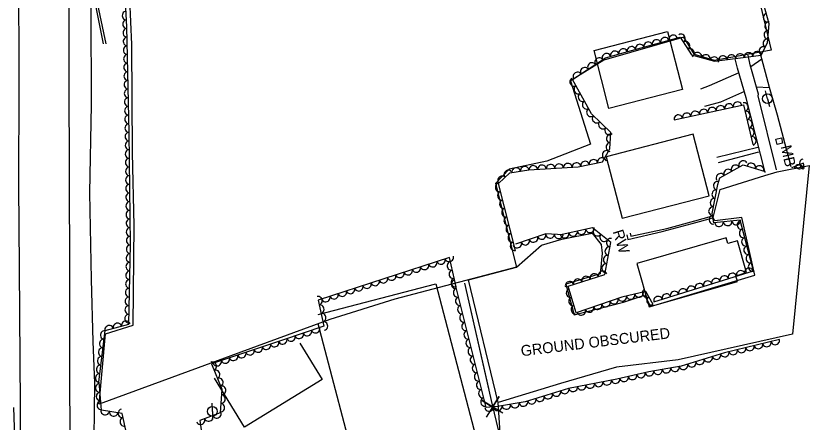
# Model space of a CAD drawing. Extents: x 1722896 to 1754269, y 648279 to 666297.
# Drawn here: x 1725769 to 1726135.7, y 663913.4 to 664101 of the extents above; entities that cross this region are included whole.
import ezdxf

# ---------------------------------------------------------------- set-up
doc = ezdxf.new("R2010")
doc.units = 0
for name, color, linetype in [('DESIGN - CENTERLINE - Proposed Text', 7, 'Continuous'), ('DESIGN - SCRATCH - User 1', 7, 'Continuous'), ('SURVEY - CENTERLINE - Preliminary', 7, 'Continuous'), ('SURVEY - CENTERLINE - Preliminary Text', 7, 'Continuous'), ('SURVEY - CONTROL with Text', 7, 'Continuous'), ('SURVEY - DTM - Breaklines', 7, 'Continuous'), ('SURVEY - VEGETATION - Features with Text', 7, 'Continuous')]:
    doc.layers.add(name, color=color, linetype=linetype)

msp = doc.modelspace()

# ---------------------------------------------------------------- linework, layer by layer
at = {"layer": 'DESIGN - CENTERLINE - Proposed Text'}
msp.add_line((1726121.95, 664043.1), (1726121.95, 664043.1), dxfattribs=at)
for points in [[(1726077.22, 664066.95), (1726043.19, 664058.18), (1726036.28, 664085), (1726070.31, 664093.78)], [(1726082.13, 664046.32), (1726041.93, 664035.87), (1726049.3, 664007.49), (1726089.51, 664017.94)], [(1726120.41, 664044.02), (1726122.89, 664044.59), (1726123.45, 664042.16), (1726120.97, 664041.58)], [(1726097.34, 663998.41), (1726056.04, 663986.6), (1726061.74, 663966.66), (1726102.63, 663978.35), (1726101.88, 663980.99), (1726106.83, 663982.41), (1726102.62, 663997.14), (1726098.07, 663995.84)]]:
    msp.add_lwpolyline(points, close=True, dxfattribs=at)
for points in [[(1726093, 664035.65), (1726112.02, 664040.3)], [(1726093.78, 664033.33), (1726112.55, 664038.13)], [(1726051.52, 663999.91), (1726051.86, 663997.66), (1726067.77, 664001.37), (1726081.65, 664005.02), (1726091.14, 664007.76)], [(1726053.04, 664000.58), (1726053.28, 663999.17), (1726069.9, 664002.79), (1726082.91, 664006.36), (1726090.65, 664008.51), (1726090.38, 664008.45)], [(1725908.68, 663963), (1725963.1, 663977.25), (1725983.29, 663900.15), (1725980.82, 663899.5), (1725984.46, 663885.6), (1725946.85, 663875.75), (1725943.25, 663889.49), (1725927.96, 663885.48), (1725908.78, 663958.71)], [(1725976.47, 663977.58), (1725989.25, 663921.4), (1725998.56, 663882.29), (1726008.07, 663844.96), (1726016.6, 663812.85), (1726028.13, 663767.43), (1726032.02, 663753.61), (1726038.83, 663727.04), (1726041.91, 663715.88), (1726060.48, 663711.15), (1726088.63, 663705.53)], [(1725976.47, 663977.58), (1725987.56, 663928.83)], [(1725900.21, 663949.89), (1725910.56, 663933.08), (1725874.73, 663911.01), (1725860.79, 663933.64)], [(1725857.39, 663939.16), (1725857.5, 663939.23)], [(1725994.19, 663917.45), (1725984.58, 663923.29), (1725989.4, 663920.32), (1725992.36, 663925.14), (1725986.41, 663915.6)]]:
    msp.add_lwpolyline(points, dxfattribs=at)
at = {"layer": 'DESIGN - SCRATCH - User 1'}
for points in [[(1725809.55, 664088.11), (1725805.45, 664108.12), (1725805.07, 664109.96), (1725804.55, 664131.33), (1725804.5, 664153.69), (1725804.21, 664188.78), (1725804.38, 664218.53), (1725804.48, 664250.49), (1725804.7, 664280.81), (1725805.06, 664317.74), (1725805.18, 664345.9), (1725805.51, 664382.38), (1725805.82, 664427), (1725805.77, 664467.08), (1725805.88, 664482.39), (1725806.62, 664514.54), (1725807.7, 664552.82), (1725809, 664590.93), (1725809.94, 664614.11)], [(1725811.21, 664614.64), (1725809.01, 664568.27), (1725807.87, 664525.22), (1725806.96, 664476.57), (1725806.92, 664426.54), (1725806.65, 664386.33), (1725806.55, 664345.18), (1725806.05, 664302.92), (1725805.75, 664256.48), (1725805.63, 664215.87), (1725805.56, 664175.8), (1725805.73, 664130.62), (1725806.11, 664109.24), (1725810.56, 664088.05)]]:
    msp.add_lwpolyline(points, dxfattribs=at)
at = {"layer": 'SURVEY - CENTERLINE - Preliminary'}
for points in [[(1726109.92, 664120.12), (1726118.23, 664085.17), (1726092, 664080.32), (1726082.8, 664083.16), (1726077.78, 664091.21), (1726040.77, 664080.57), (1726025.46, 664071.03), (1726034.65, 664041.67), (1726014.52, 664033.95), (1725997.1, 664030.15), (1725990.79, 664023.6), (1726000.5, 663984.87), (1725944.23, 663970.15), (1725914.18, 663960.71), (1725807.59, 663921.69), (1725810.39, 663954.19), (1725823.16, 663958.11), (1725823.63, 664004.1), (1725822.95, 664037.66), (1725822.67, 664087.73), (1725821.24, 664119.26)], [(1726135.73, 664031.95), (1726128.05, 663953.96), (1726075.23, 663942.2), (1726046.64, 663938.73), (1726020.72, 663931.21), (1725992, 663922.36), (1725978.23, 663979.04), (1726000.5, 663984.87), (1726011.94, 663995.14), (1726021.46, 663997.8), (1726035.46, 664000.58), (1726039.66, 663995.4), (1726040.12, 663991.34), (1726039.05, 663981.91), (1726023.27, 663977.13), (1726027.03, 663962.94), (1726049.84, 663968.83), (1726059.57, 663972), (1726062.35, 663966.76), (1726110.69, 663981.21), (1726104.67, 664007.79), (1726092.08, 664006.34), (1726091.36, 664007.83), (1726094.65, 664020.86), (1726115.19, 664027.29), (1726120.97, 664028.93), (1726135.73, 664031.95)]]:
    msp.add_lwpolyline(points, dxfattribs=at)
at = {"layer": 'SURVEY - CENTERLINE - Preliminary Text'}
for points in [[(1725801.9, 664902.98), (1725794.09, 664850.95), (1725789.15, 664809.58), (1725783.94, 664755.45), (1725779.93, 664707.15), (1725776.28, 664651.75), (1725773.96, 664606.06), (1725772.39, 664548.53), (1725771.2, 664484.76), (1725770.98, 664430.19), (1725770.44, 664376.83), (1725770.27, 664318.87), (1725770.24, 664272.95), (1725769.88, 664230.34), (1725770.2, 664176.88), (1725770.2, 664123.86), (1725770.38, 664069.19), (1725770.29, 664022.6), (1725770.48, 663984.72), (1725770.92, 663920.94)], [(1725824.54, 664897.87), (1725817.95, 664853.26), (1725812.81, 664810.26), (1725808.59, 664768.78), (1725804.64, 664721.76), (1725800.65, 664668.84), (1725797.89, 664617.77), (1725795.92, 664570.1), (1725794.7, 664517.8), (1725794.26, 664465.85), (1725794.04, 664417.46), (1725793.7, 664368.7), (1725793.43, 664309.68), (1725793.32, 664262.92), (1725793.17, 664211.43), (1725793.2, 664169.22), (1725793.52, 664124.78), (1725793.49, 664072.64), (1725793.72, 664026.28), (1725793.85, 663983.07), (1725793.75, 663928.15)], [(1725825.87, 664847.96), (1725822.06, 664820.95), (1725819.88, 664786.45), (1725817.42, 664751.99), (1725814.35, 664714.62), (1725811.46, 664672.62), (1725808.95, 664633.43), (1725807.16, 664600.37), (1725805.58, 664552.66), (1725804.74, 664503.84), (1725804.48, 664455.23), (1725804.06, 664411.95), (1725804.54, 664365.54), (1725803.43, 664325.01), (1725803.78, 664281.14), (1725803.72, 664242.77), (1725803.23, 664197.73), (1725803.14, 664146.83), (1725803.69, 664103.99), (1725803.87, 664059.83), (1725803.1, 664019.2), (1725803.8, 663979.2), (1725804.62, 663950.55), (1725805.38, 663931.3)], [(1726108.44, 664078.43), (1726107.48, 664082.84)], [(1726113.12, 664083.64), (1726117.31, 664068.02), (1726120.91, 664055.26), (1726127.29, 664031.38)], [(1726102.67, 664076.83), (1726101.52, 664081.16)], [(1726113.84, 664080.98), (1726108.71, 664077.46)], [(1726115.36, 664028.58), (1726106.66, 664063.11), (1726102.67, 664076.83)], [(1726112.28, 664064.81), (1726108.44, 664078.43)], [(1726103.28, 664074.73), (1726089.45, 664068.64), (1726085.58, 664067.18)], [(1726117.38, 664067.77), (1726111.36, 664068.06)], [(1726105.81, 664066.02), (1726094.76, 664061.19), (1726087.43, 664059.07)], [(1726120.69, 664029.9), (1726112.19, 664064.07), (1726112.28, 664064.81)], [(1725793.75, 663928.15), (1725794.27, 663884.6), (1725794.44, 663846.79), (1725794.74, 663777.92), (1725795.03, 663737.56), (1725795.16, 663695.93), (1725795.35, 663656.31), (1725794.99, 663621.4), (1725794.82, 663587.82), (1725794.68, 663549.78), (1725794.72, 663535.97)], [(1725805.38, 663931.3), (1725805.06, 663906.05), (1725804.74, 663869.06), (1725805.03, 663835.48), (1725804.99, 663801.18), (1725805.12, 663769.95), (1725805.35, 663737.8), (1725805.5, 663711.01), (1725805.48, 663697.58), (1725805.26, 663657.83), (1725805.02, 663620.78), (1725804.63, 663584.05), (1725804.26, 663547.19)], [(1725770.92, 663920.94), (1725770.93, 663878.35), (1725771.25, 663840.71), (1725769.22, 663887.98), (1725768.12, 663920.16)], [(1725992.94, 663908.4), (1725992, 663922.36)]]:
    msp.add_lwpolyline(points, dxfattribs=at)
at = {"layer": 'SURVEY - DTM - Breaklines'}
for p, q in [((1726116.47, 664062.7), (1726115.5, 664066.32)), ((1726116.47, 664062.7), (1726117.43, 664059.07)), ((1725859.86, 663918.32), (1725859.77, 663922.07)), ((1725859.86, 663918.32), (1725859.95, 663914.57))]:
    msp.add_line(p, q, dxfattribs=at)
for centre in [(1726116.47, 664062.7), (1725859.86, 663918.32)]:
    msp.add_circle(centre, 2.25, dxfattribs=at)
at = {"layer": 'SURVEY - VEGETATION - Features with Text'}
for points in [[(1725807.43, 663931.74), (1725810.23, 663955.63), (1725821.17, 663958.57), (1725822.02, 663995.36), (1725821.37, 664047.08), (1725820.37, 664095.94), (1725817.64, 664145.42)], [(1725999.93, 663992.68), (1725992.14, 664023.59), (1725997.39, 664028.55), (1726006.21, 664029.82), (1726028.9, 664031.27), (1726040.23, 664033.58), (1726043.66, 664039.61), (1726044.12, 664047.1), (1726035.13, 664055.68), (1726026.37, 664071.59), (1726033.11, 664076.01), (1726041.54, 664081.59), (1726050.23, 664084.02), (1726076.18, 664091.1), (1726081.28, 664082.97), (1726091.97, 664080.11), (1726113.58, 664082.86), (1726116.42, 664088.47), (1726117.23, 664097.31), (1726111.83, 664116.86)], [(1726073.3, 664052.94), (1726105.39, 664059.97), (1726109.75, 664041.54)], [(1726063.99, 663968.94), (1726109.96, 663983.24), (1726103.79, 664006.56), (1726091.64, 664005.33), (1726090.97, 664009.76), (1726093.51, 664023.03), (1726094.44, 664026.11), (1726105.25, 664032.2), (1726115.42, 664029.07)], [(1726133.18, 664032.89), (1726127.63, 664030.79)], [(1726063.56, 663967.7), (1726060.19, 663973.65), (1726049.21, 663971.09), (1726028.02, 663963.84), (1726024.4, 663976.21), (1726041.22, 663981.53), (1726043.99, 663996.27), (1726035.55, 664003.02), (1726021.5, 664000.06)], [(1726021.95, 663999.88), (1726013.99, 664000.35), (1726000.03, 663995.47)], [(1725972.51, 663975.82), (1725969.42, 663989.4), (1725908.71, 663969.69), (1725911.32, 663957.68), (1725892.34, 663951.28), (1725859.43, 663940.3), (1725864.25, 663928.51), (1725863.45, 663917.7), (1725854.06, 663914.03), (1725860.68, 663868.53), (1725865.33, 663831.05), (1725865.25, 663814), (1725854.4, 663811.29), (1725844.66, 663810.97), (1725847.13, 663833.95), (1725846.29, 663842.78), (1725828.72, 663846.29), (1725825.74, 663870.51), (1725822.49, 663897.85), (1725818.18, 663917.4), (1725808.57, 663918.88), (1725807.5, 663931.83)], [(1726122, 663951.47), (1726096.57, 663945.37), (1726076.5, 663939.13), (1726061.68, 663936.55), (1726046.79, 663933.21), (1726024.5, 663928.93), (1726004.52, 663922.69), (1725991.68, 663920.52), (1725986.39, 663920.16), (1725972.09, 663977.41)]]:
    msp.add_lwpolyline(points, dxfattribs=at)
for centre, major_axis in [((1725820.08, 664101.16), (-0.11, 2)), ((1726116.44, 664100.17), (-0.53, 1.93)), ((1725820.31, 664097.16), (-0.11, 2)), ((1726117.14, 664096.28), (0.18, 1.99)), ((1725820.43, 664093.17), (-0.04, 2)), ((1726116.77, 664092.3), (0.18, 1.99)), ((1725820.51, 664089.17), (-0.04, 2)), ((1726065.16, 664088.09), (1.93, 0.53)), ((1726069.02, 664089.14), (1.93, 0.53)), ((1726072.88, 664090.19), (1.93, 0.53)), ((1726076.49, 664090.61), (1.06, -1.69)), ((1726116.35, 664088.33), (0.9, 1.79)), ((1725820.59, 664085.17), (-0.04, 2)), ((1726049.73, 664083.88), (1.93, 0.54)), ((1726053.58, 664084.93), (1.93, 0.53)), ((1726057.44, 664085.98), (1.93, 0.53)), ((1726061.3, 664087.04), (1.93, 0.53)), ((1726078.61, 664087.22), (1.06, -1.69)), ((1726080.74, 664083.83), (1.06, -1.69)), ((1726114.54, 664084.76), (0.9, 1.79)), ((1725820.67, 664081.17), (-0.04, 2)), ((1726042.02, 664081.73), (1.93, 0.54)), ((1726045.87, 664082.8), (1.93, 0.54)), ((1726084.16, 664082.2), (1.93, -0.52)), ((1726088.03, 664081.16), (1.93, -0.52)), ((1726091.89, 664080.13), (1.93, -0.52)), ((1726095.86, 664080.6), (1.98, 0.25)), ((1726099.82, 664081.11), (1.98, 0.25)), ((1726103.79, 664081.61), (1.98, 0.25)), ((1726107.76, 664082.12), (1.98, 0.25)), ((1726111.73, 664082.62), (1.98, 0.25)), ((1725820.76, 664077.17), (-0.04, 2)), ((1726035.28, 664077.45), (1.67, 1.1)), ((1726038.62, 664079.66), (1.67, 1.1)), ((1725820.84, 664073.17), (-0.04, 2)), ((1726028.6, 664073.05), (1.67, 1.1)), ((1726031.95, 664075.25), (1.67, 1.1)), ((1725820.92, 664069.17), (-0.04, 2)), ((1726027.01, 664070.42), (-0.96, 1.75)), ((1726028.94, 664066.92), (-0.96, 1.75)), ((1725821, 664065.17), (-0.04, 2)), ((1726030.87, 664063.42), (-0.96, 1.75)), ((1725821.08, 664061.17), (-0.04, 2)), ((1726032.8, 664059.91), (-0.96, 1.75)), ((1726098.7, 664058.5), (1.95, 0.43)), ((1726102.6, 664059.36), (1.95, 0.43)), ((1726105.65, 664058.85), (0.46, -1.95)), ((1725821.16, 664057.17), (-0.04, 2)), ((1726034.73, 664056.41), (-0.96, 1.75)), ((1726083.07, 664055.08), (1.95, 0.43)), ((1726086.97, 664055.94), (1.95, 0.43)), ((1726090.88, 664056.79), (1.95, 0.43)), ((1726094.79, 664057.65), (1.95, 0.43)), ((1726106.57, 664054.96), (0.46, -1.95)), ((1725821.24, 664053.17), (-0.04, 2)), ((1726037.43, 664053.49), (-1.45, 1.38)), ((1726075.25, 664053.37), (1.95, 0.43)), ((1726079.16, 664054.23), (1.95, 0.43)), ((1726107.5, 664051.07), (0.46, -1.95)), ((1725821.33, 664049.18), (-0.04, 2)), ((1726040.32, 664050.73), (-1.45, 1.38)), ((1726043.21, 664047.97), (-1.45, 1.38)), ((1726108.42, 664047.17), (0.46, -1.95)), ((1725821.39, 664045.18), (-0.03, 2)), ((1726043.95, 664044.36), (0.12, 2)), ((1725821.44, 664041.18), (-0.03, 2)), ((1726043.71, 664040.37), (0.12, 2)), ((1726109.34, 664043.28), (0.46, -1.95)), ((1725821.49, 664037.18), (-0.03, 2)), ((1726042.06, 664036.79), (0.99, 1.74)), ((1725821.54, 664033.18), (-0.03, 2)), ((1726036.01, 664032.72), (1.96, 0.4)), ((1726039.93, 664033.52), (1.96, 0.4)), ((1726133.19, 664032.83), (-0.36, 1.97)), ((1725821.59, 664029.18), (-0.03, 2)), ((1726000.27, 664028.96), (1.98, 0.28)), ((1726004.23, 664029.53), (1.98, 0.28)), ((1726008.2, 664029.94), (2, 0.13)), ((1726012.2, 664030.2), (2, 0.13)), ((1726016.19, 664030.45), (2, 0.13)), ((1726020.18, 664030.71), (2, 0.13)), ((1726024.17, 664030.96), (2, 0.13)), ((1726028.16, 664031.22), (2, 0.13)), ((1726032.1, 664031.92), (1.96, 0.4)), ((1726101.68, 664030.19), (1.74, 0.98)), ((1726105.17, 664032.16), (1.74, 0.98)), ((1726108.98, 664031.05), (1.91, -0.59)), ((1726112.81, 664029.87), (1.91, -0.59)), ((1726130.96, 664030.34), (1.97, -0.36)), ((1726131.3, 664032.18), (-1.87, -0.71)), ((1725821.64, 664025.18), (-0.03, 2)), ((1725993.69, 664025.05), (1.45, 1.37)), ((1725996.6, 664027.8), (1.45, 1.37)), ((1726094.71, 664026.27), (1.74, 0.98)), ((1726098.2, 664028.23), (1.74, 0.98)), ((1725992.6, 664021.77), (-0.49, 1.94)), ((1726093.42, 664022.57), (0.38, 1.96)), ((1725821.69, 664021.18), (-0.03, 2)), ((1725993.58, 664017.9), (-0.49, 1.94)), ((1726092.67, 664018.64), (0.38, 1.96)), ((1725821.74, 664017.18), (-0.03, 2)), ((1726091.92, 664014.72), (0.38, 1.96)), ((1725821.79, 664013.18), (-0.03, 2)), ((1725994.55, 664014.02), (-0.49, 1.94)), ((1726091.16, 664010.79), (0.38, 1.96)), ((1725821.84, 664009.18), (-0.03, 2)), ((1725995.53, 664010.14), (-0.49, 1.94)), ((1726091.41, 664006.84), (-0.3, 1.98)), ((1725821.89, 664005.18), (-0.03, 2)), ((1725996.51, 664006.26), (-0.49, 1.94)), ((1726094.09, 664005.58), (-1.99, -0.2)), ((1726098.07, 664005.98), (-1.99, -0.2)), ((1726102.05, 664006.38), (-1.99, -0.2)), ((1726104.36, 664004.38), (-0.51, 1.93)), ((1725821.94, 664001.18), (-0.03, 2)), ((1725997.49, 664002.38), (-0.49, 1.94)), ((1726026.59, 664001.13), (-1.96, -0.41)), ((1726030.51, 664001.96), (-1.96, -0.41)), ((1726034.42, 664002.78), (-1.96, -0.41)), ((1726037.77, 664001.24), (-1.56, 1.25)), ((1726105.39, 664000.51), (-0.51, 1.93)), ((1725822, 663997.18), (-0.03, 2)), ((1725998.46, 663998.5), (-0.49, 1.94)), ((1726008.3, 663998.36), (-1.89, -0.66)), ((1726012.08, 663999.68), (-1.89, -0.66)), ((1726015.96, 664000.23), (-2, 0.12)), ((1726019.95, 663999.99), (-2, 0.12)), ((1726022.68, 664000.31), (-1.96, -0.41)), ((1726040.89, 663998.74), (-1.56, 1.25)), ((1726043.98, 663996.23), (0.37, 1.97)), ((1726106.41, 663996.64), (-0.51, 1.93)), ((1725821.97, 663993.18), (0.05, 2)), ((1725999.44, 663994.62), (-0.49, 1.94)), ((1726000.75, 663995.72), (-1.89, -0.66)), ((1726004.52, 663997.04), (-1.89, -0.66)), ((1726043.24, 663992.3), (0.37, 1.97)), ((1726107.43, 663992.78), (-0.51, 1.93)), ((1725821.88, 663989.18), (0.05, 2)), ((1726042.51, 663988.37), (0.37, 1.97)), ((1726108.46, 663988.91), (-0.51, 1.93)), ((1725821.78, 663985.18), (0.05, 2)), ((1725961.74, 663986.91), (-1.9, -0.62)), ((1725965.54, 663988.14), (-1.9, -0.62)), ((1725969.35, 663989.38), (-1.9, -0.62)), ((1725970.29, 663985.57), (-0.45, 1.95)), ((1726109.48, 663985.04), (-0.51, 1.93)), ((1725821.69, 663981.18), (0.05, 2)), ((1725950.32, 663983.2), (-1.9, -0.62)), ((1725954.13, 663984.44), (-1.9, -0.62)), ((1725957.93, 663985.67), (-1.9, -0.62)), ((1725971.18, 663981.67), (-0.45, 1.95)), ((1726040.23, 663981.21), (1.91, 0.6)), ((1726041.77, 663984.44), (0.37, 1.97)), ((1726104.09, 663981.42), (1.91, 0.59)), ((1726107.91, 663982.61), (1.91, 0.59)), ((1725938.91, 663979.49), (-1.9, -0.62)), ((1725942.72, 663980.73), (-1.9, -0.62)), ((1725946.52, 663981.96), (-1.9, -0.62)), ((1725972.07, 663977.77), (-0.45, 1.95)), ((1726028.79, 663977.6), (1.91, 0.6)), ((1726032.6, 663978.8), (1.91, 0.6)), ((1726036.42, 663980.01), (1.91, 0.6)), ((1726092.64, 663977.86), (1.91, 0.59)), ((1726096.45, 663979.04), (1.91, 0.59)), ((1726100.27, 663980.23), (1.91, 0.59)), ((1725821.6, 663977.18), (0.05, 2)), ((1725927.5, 663975.79), (-1.9, -0.62)), ((1725931.3, 663977.02), (-1.9, -0.62)), ((1725935.11, 663978.26), (-1.9, -0.62)), ((1725972.2, 663976.99), (-0.48, 1.94)), ((1726024.98, 663976.39), (1.91, 0.6)), ((1726081.18, 663974.29), (1.91, 0.59)), ((1726085, 663975.48), (1.91, 0.59)), ((1726088.82, 663976.67), (1.91, 0.59)), ((1725821.51, 663973.19), (0.05, 2)), ((1725916.08, 663972.08), (-1.9, -0.62)), ((1725919.89, 663973.32), (-1.9, -0.62)), ((1725923.69, 663974.55), (-1.9, -0.62)), ((1725973.17, 663973.11), (-0.48, 1.94)), ((1726025.35, 663972.95), (-0.56, 1.92)), ((1726053.21, 663972.03), (-1.95, -0.45)), ((1726057.11, 663972.93), (-1.95, -0.45)), ((1726060.6, 663972.92), (-0.99, 1.74)), ((1726069.72, 663970.72), (1.91, 0.59)), ((1726073.54, 663971.91), (1.91, 0.59)), ((1726077.36, 663973.1), (1.91, 0.59)), ((1725821.41, 663969.19), (0.05, 2)), ((1725908.76, 663969.44), (0.42, -1.95)), ((1725912.28, 663970.84), (-1.9, -0.62)), ((1725974.14, 663969.23), (-0.48, 1.94)), ((1726026.48, 663969.11), (-0.56, 1.92)), ((1726041.75, 663968.54), (-1.89, -0.65)), ((1726045.53, 663969.83), (-1.89, -0.65)), ((1726049.32, 663971.12), (-1.95, -0.45)), ((1726062.57, 663969.44), (-0.99, 1.74)), ((1726065.9, 663969.54), (1.91, 0.59)), ((1725821.32, 663965.19), (0.05, 2)), ((1725909.61, 663965.53), (0.42, -1.95)), ((1725975.11, 663965.35), (-0.48, 1.94)), ((1726027.6, 663965.28), (-0.56, 1.92)), ((1726030.39, 663964.65), (-1.89, -0.65)), ((1726034.18, 663965.95), (-1.89, -0.65)), ((1726037.96, 663967.24), (-1.89, -0.65)), ((1725821.23, 663961.19), (0.05, 2)), ((1725910.46, 663961.62), (0.42, -1.95)), ((1725976.07, 663961.47), (-0.48, 1.94)), ((1725812.11, 663956.13), (1.93, 0.52)), ((1725815.97, 663957.17), (1.93, 0.52)), ((1725819.84, 663958.21), (1.93, 0.52)), ((1725911.31, 663957.72), (0.42, -1.95)), ((1725977.04, 663957.59), (-0.48, 1.94)), ((1725809.99, 663953.59), (0.23, 1.99)), ((1725899.98, 663953.86), (-1.9, -0.64)), ((1725903.77, 663955.13), (-1.9, -0.64)), ((1725907.56, 663956.41), (-1.9, -0.64)), ((1725978.01, 663953.71), (-0.48, 1.94)), ((1725809.53, 663949.62), (0.23, 1.99)), ((1725888.61, 663950.03), (-1.9, -0.63)), ((1725892.4, 663951.3), (-1.9, -0.64)), ((1725896.19, 663952.58), (-1.9, -0.64)), ((1725978.98, 663949.83), (-0.48, 1.94)), ((1726116.16, 663950.08), (-1.94, -0.47)), ((1726120.05, 663951.01), (-1.94, -0.47)), ((1725809.06, 663945.64), (0.23, 1.99)), ((1725877.22, 663946.24), (-1.9, -0.63)), ((1725881.02, 663947.5), (-1.9, -0.63)), ((1725884.81, 663948.77), (-1.9, -0.63)), ((1725979.95, 663945.94), (-0.48, 1.94)), ((1726100.61, 663946.34), (-1.94, -0.47)), ((1726104.5, 663947.28), (-1.94, -0.47)), ((1726108.39, 663948.21), (-1.94, -0.47)), ((1726112.27, 663949.14), (-1.94, -0.47)), ((1725808.6, 663941.67), (0.23, 1.99)), ((1725865.84, 663942.44), (-1.9, -0.63)), ((1725869.64, 663943.71), (-1.9, -0.63)), ((1725873.43, 663944.97), (-1.9, -0.63)), ((1725980.92, 663942.06), (-0.48, 1.94)), ((1726089.07, 663943.04), (-1.91, -0.59)), ((1726092.89, 663944.23), (-1.91, -0.59)), ((1726096.72, 663945.41), (-1.94, -0.47)), ((1725808.13, 663937.7), (0.23, 1.99)), ((1725859.9, 663939.16), (0.76, -1.85)), ((1725862.05, 663941.18), (-1.9, -0.63)), ((1725981.89, 663938.18), (-0.48, 1.94)), ((1726077.62, 663939.48), (-1.91, -0.59)), ((1726081.44, 663940.67), (-1.91, -0.59)), ((1726085.26, 663941.85), (-1.91, -0.59)), ((1725807.67, 663933.72), (0.23, 1.99)), ((1725861.41, 663935.45), (0.76, -1.85)), ((1725982.86, 663934.3), (-0.48, 1.94)), ((1726057.98, 663935.72), (-1.95, -0.44)), ((1726061.89, 663936.58), (-1.97, -0.34)), ((1726065.83, 663937.27), (-1.97, -0.34)), ((1726069.77, 663937.96), (-1.97, -0.34)), ((1726073.71, 663938.65), (-1.97, -0.34)), ((1725862.92, 663931.75), (0.76, -1.85)), ((1725983.83, 663930.42), (-0.48, 1.94)), ((1726038.41, 663931.6), (-1.96, -0.38)), ((1726042.34, 663932.36), (-1.96, -0.38)), ((1726046.27, 663933.12), (-1.96, -0.38)), ((1726050.18, 663933.97), (-1.95, -0.44)), ((1726054.08, 663934.85), (-1.95, -0.44)), ((1725807.72, 663929.13), (-0.17, 1.99)), ((1725864.21, 663928.01), (-0.15, -1.99)), ((1725984.8, 663926.54), (-0.48, 1.94)), ((1726022.75, 663928.38), (-1.91, -0.6)), ((1726026.63, 663929.34), (-1.96, -0.38)), ((1726030.56, 663930.09), (-1.96, -0.38)), ((1726034.49, 663930.85), (-1.96, -0.38)), ((1725808.06, 663925.14), (-0.17, 1.99)), ((1725863.92, 663924.02), (-0.15, -1.99)), ((1725985.77, 663922.66), (-0.48, 1.94)), ((1726011.3, 663924.81), (-1.91, -0.6)), ((1726015.12, 663926), (-1.91, -0.6)), ((1726018.93, 663927.19), (-1.91, -0.6)), ((1725808.39, 663921.16), (-0.17, 1.99)), ((1725863.62, 663920.03), (-0.15, -1.99)), ((1725991.8, 663920.54), (-1.97, -0.33)), ((1725995.75, 663921.21), (-1.97, -0.33)), ((1725999.69, 663921.87), (-1.97, -0.33)), ((1726003.63, 663922.54), (-1.97, -0.33)), ((1726007.48, 663923.61), (-1.91, -0.6)), ((1725810.27, 663918.62), (-1.98, 0.31)), ((1725814.23, 663918.01), (-1.98, 0.31)), ((1725818.18, 663917.4), (-0.43, 1.95)), ((1725861.91, 663917.09), (-1.86, -0.73)), ((1725987.81, 663920.26), (-2, -0.14)), ((1725819.04, 663913.49), (-0.43, 1.95)), ((1725854.45, 663914.19), (-1.86, -0.73)), ((1725858.18, 663915.64), (-1.86, -0.73))]:
    msp.add_ellipse(centre, major_axis=major_axis, ratio=0.940188, start_param=0, end_param=3.141593, dxfattribs=at)

# ---------------------------------------------------------------- texts
at = {"layer": 'DESIGN - CENTERLINE - Proposed Text'}
msp.add_text('MB', height=5, rotation=283.0077, dxfattribs=at).set_placement((1726122.52, 664040.66))
at = {"layer": 'SURVEY - CENTERLINE - Preliminary'}
msp.add_text('GROUND OBSCURED', height=5, rotation=6.9322, dxfattribs=at).set_placement((1726002.73, 663943.73))
at = {"layer": 'SURVEY - CONTROL with Text'}
msp.add_text('RW', height=5, rotation=286.9698, dxfattribs=at).set_placement((1726044.87, 664001.39))

doc.saveas('drawing.dxf')
